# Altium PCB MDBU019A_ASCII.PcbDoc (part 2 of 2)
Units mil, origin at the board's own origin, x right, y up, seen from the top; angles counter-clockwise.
Board outline 2500 x 2300 mil, 2 copper layers (Top Layer, Bottom Layer), stack 62 mil thick; 48 components, 19 nets, 113 pads, 75 vias.
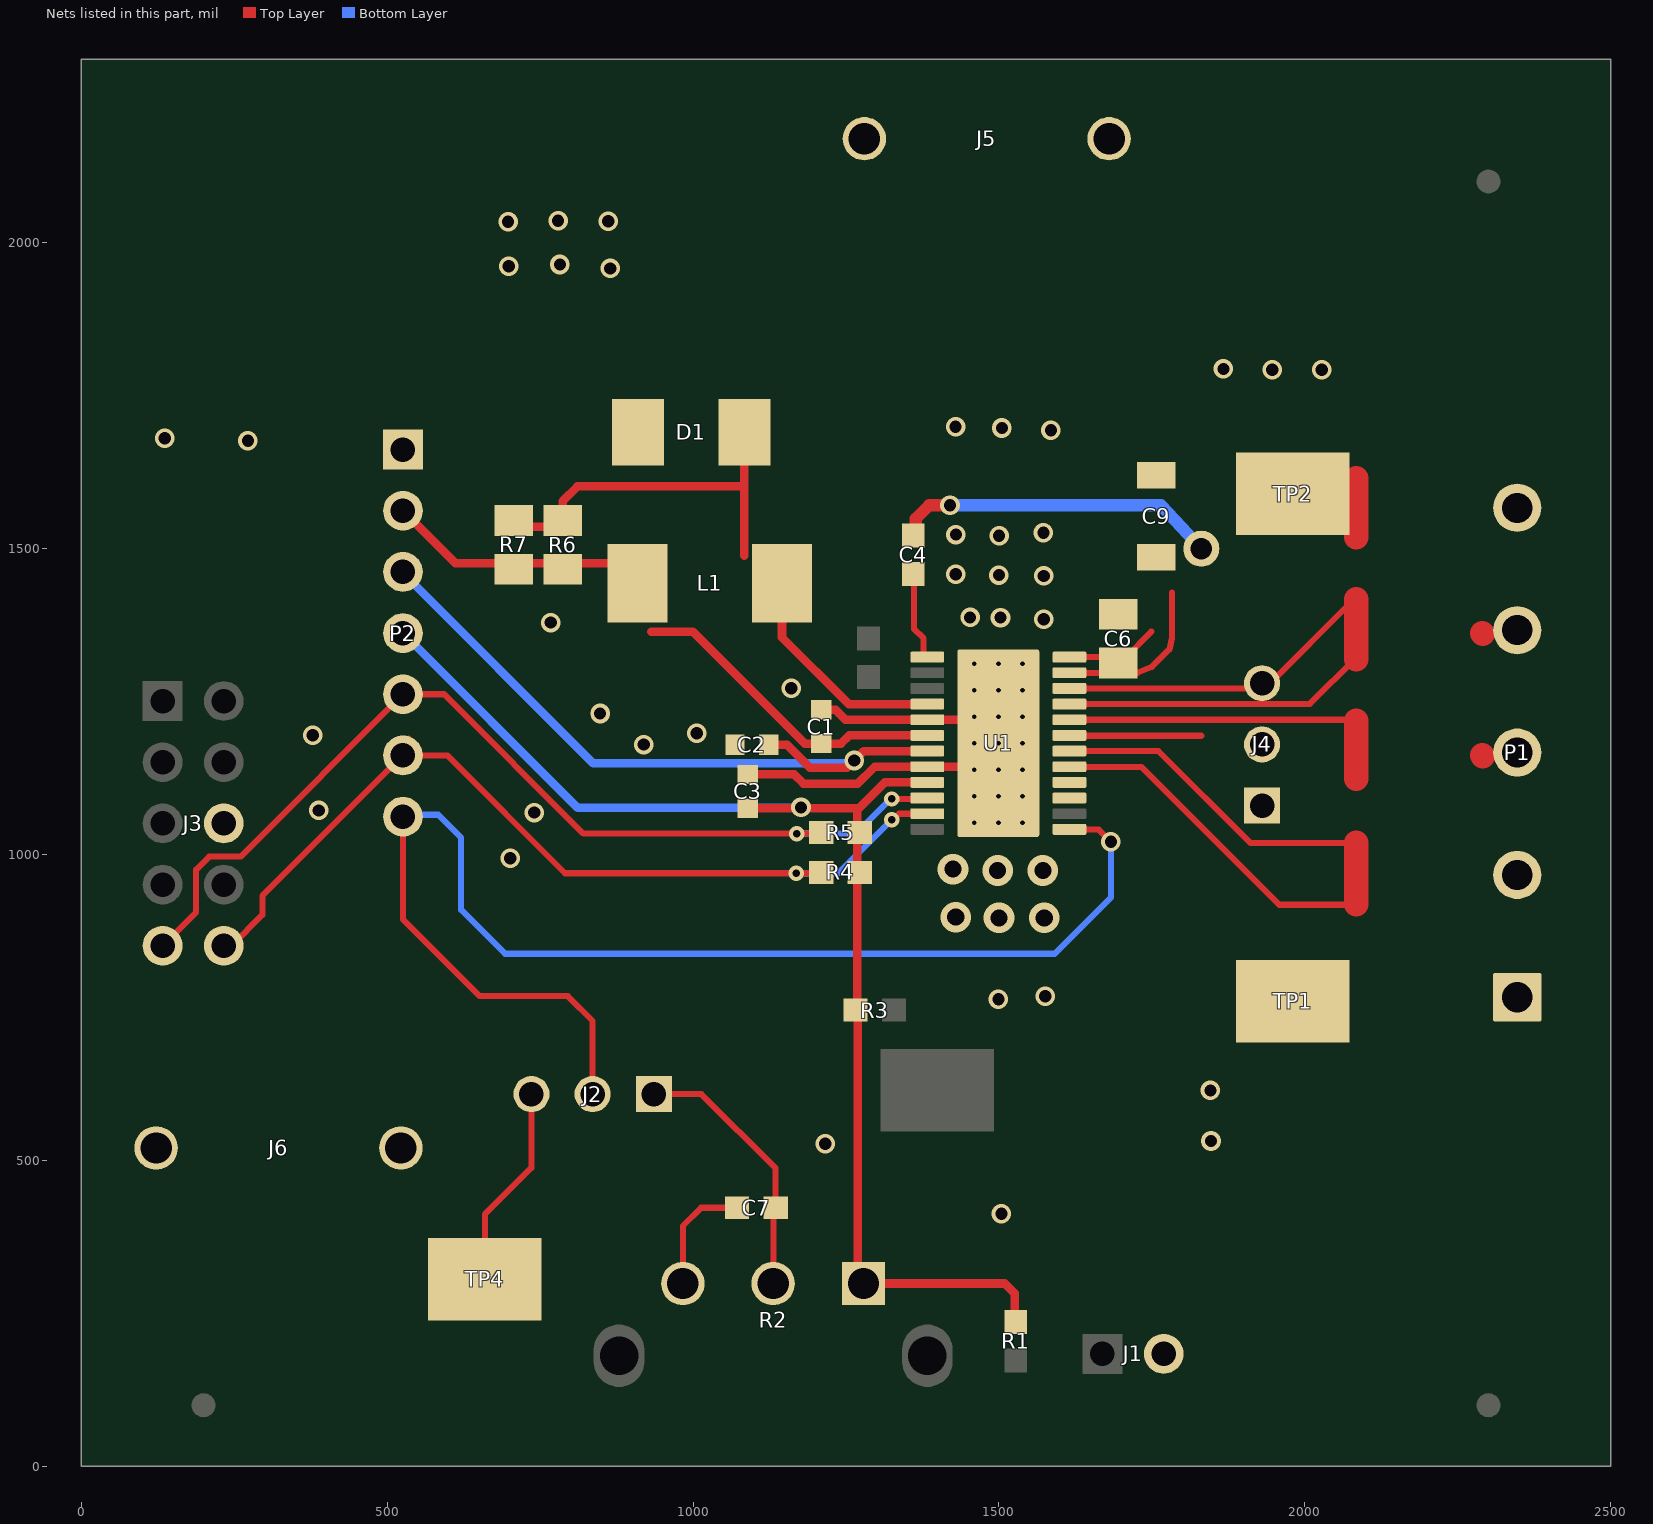
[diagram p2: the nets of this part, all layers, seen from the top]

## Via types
v1: diameter 32, hole 20, Top Layer to Bottom Layer, 44 vias
v2: diameter 19.68, hole 7.87, Top Layer to Bottom Layer, 15 vias
v3: diameter 19.68, hole 7.87, Top Layer to Bottom Layer, tented both sides, 6 vias
v4: diameter 50, hole 28, Top Layer to Bottom Layer, 6 vias
v5: diameter 25, hole 12, Top Layer to Bottom Layer, 4 vias

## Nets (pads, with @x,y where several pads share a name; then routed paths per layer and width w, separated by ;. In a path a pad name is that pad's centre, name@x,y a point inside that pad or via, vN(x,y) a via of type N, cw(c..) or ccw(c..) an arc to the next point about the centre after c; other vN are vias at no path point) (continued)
GND: C1.2 C2.1 C3.1 C6.1 C7.2 C9.2 D1.2 J1.2 J3.6 J5.1 J5.2 J6.1 J6.2 P1.1 P2.1 R2.3 TP1.1 U1.5 U1.8 U1.15 U1.16 U1.25@1499,1182 | length 980.1
  Top Layer w10: R2.3@983.36,299 983.36,392.96 1013.3,422.9 C7.2@1076.08,422.9 ; U1.25@1510,1100 U1.25@1517.7,1092.3 ; U1.25@1510,1110 U1.25@1517.3,1117.3
  Top Layer w14: C3.1@1089.2,1130.99 1165.53,1130.99 1180.49,1116.03 1269.36,1116.03 1295.06,1141.72 ; C1.2@1209.51,1236.59 1232.99,1236.59 1249.19,1220.39 U1.5@1382.86,1220.39 1460.61,1220.39 v2(1499,1182) 1460.61,1143.61 U1.8@1382.86,1143.61 1296.95,1143.61
  Bottom Layer w20: 1481,1095 1486,1090
  other v1: 1504.07,413.03 1216.28,527.43 1846.5,531.89 1845.64,614.54 1499.09,763.65 1575.68,768.64 701.43,994.21 740.3,1068.69 388.16,1072.18 919.43,1179.83 378.28,1195.22 1006.12,1198.24 848.06,1230.54 1160.66,1272.04 767.5,1379.19 1573.05,1384.73 1502.55,1387.35 1452.74,1387.6 1573.3,1455.52 1499.97,1456.81 1429.22,1458.1 1500.23,1520.99 1429.6,1522.97 1572.72,1526.09 272.52,1676.56 136.41,1680.59 1584.85,1693.59 1504.9,1697.24 1429.07,1699.42 1946.61,1792.44 2027.41,1792.44 1866.86,1793.76 864.78,1957.97 698.64,1961.44 782.45,1964.42 697.65,2034.35 861.51,2035.16 779.48,2035.84
  other v2: 1459.63,1095.39 1499,1095.39 1538.37,1095.39 1459.63,1138.69 1499,1138.69 1538.37,1138.69 1459.63,1182 1538.37,1182 1459.63,1225.31 1499,1225.31 1538.37,1225.31 1459.63,1268.61 1499,1268.61 1538.37,1268.61
  other v3: 1459.63,1052.08 1499,1052.08 1538.37,1052.08 1459.63,1311.92 1499,1311.92 1538.37,1311.92
  other v4: 1500.01,896.65 1574.03,896.65 1429.3,897.76 1497.8,973.99 1571.82,973.99 1424.88,976.2
NetC7_1: C7.1 J2.1 R2.2 | length 483.1
  Top Layer w10: J2.1@935.93,608.59 1013.57,608.59 1134.84,487.32 C7.1@1134.84,419.25 ; R2.2@1118.39,286.39 1113.16,286.39 1113.16,306.39 1123.61,316.84 R2.2@1125.52,316.84 ; R2.2@1131,299 1131.2,299.2 C7.1@1131.2,422.9
PWMIN: J2.3 TP4.1 | length 340.5
  Top Layer w10: TP4.1@629.24,311.31 TP4.1@633.47,307.09 ; TP4.1@659.68,305.63 659.68,411.96 735.93,488.2 J2.3@735.93,608.59
SCL: J3.9 P2.5 R5.2 U1.10 | length 1621.2
  Top Layer w10: J3.9@133.08,851 187.76,905.68 187.76,975.54 209.03,996.82 260.7,996.82 P2.5@525.93,1262.05 593.12,1262.05 820.87,1034.3 v5(1169.36,1034.3) 1211.74,1034.3 R5.2@1213.44,1036 ; v5(1325,1091) 1381.43,1091 U1.10@1382.86,1092.43
  Bottom Layer w10: v5(1169.36,1034.3) 1266.46,1034.3 ; 1268.59,1036.43 1323.16,1091 v5(1325,1091)
SDA: J3.10 P2.6 R4.2 U1.11 | length 1463.5
  Top Layer w10: J3.10@233.08,851 245.75,851 296.24,901.48 296.24,932.36 P2.6@525.93,1162.05 598.2,1162.05 790.73,969.52 v5(1168.49,969.52) 1211.96,969.52 R4.2@1213.44,971 ; P2.6@535,1188.82 P2.6@535,1190 ; v5(1325,1057) 1326.84,1057 1336.68,1066.84 U1.11@1382.86,1066.84
  Bottom Layer w10: v5(1168.49,969.52) 1237.52,969.52 v5(1325,1057)
SPEED: J2.2 P2.7 U1.13 | length 2285.8
  Top Layer w10: P2.7@525.93,1062.05 525.93,894.1 651.22,768.81 795.14,768.81 835.93,728.03 J2.2@835.93,608.59 ; U1.13@1615.14,1041.25 1658.11,1041.25 1658.59,1040.77 1663.23,1040.77 v1(1683,1021)
  Bottom Layer w10: P2.7@525.93,1062.05 P2.7@525.93,1038.5 ; P2.7@530.03,1034.4 P2.7@525.93,1038.5 ; v1(1683,1021) 1683,929.63 1591.22,837.86 692.77,837.86 620.95,909.69 620.95,1027.71 583.51,1065.15 499.28,1065.15 P2.7@525.93,1038.5
SW: D1.1 L1.2 R6.2 R7.2 U1.4 | length 955.9
  Top Layer w14: R7.2@707.14,1535.56 R6.2@756.58,1535.56 ; R6.2@787.14,1535.56 787.14,1577.72 811.18,1601.76 1083.8,1601.76 ; 1083.8,1488.63 1083.8,1601.76 ; D1.1@1083.8,1690.24 1083.8,1601.76 ; L1.2@1145.55,1428.46 1145.41,1355.05 1254.49,1245.98 U1.4@1382.86,1245.98
U: J4.1 P1.2 U1.17 U1.18 | length 1202.6
  Top Layer w10: U1.17@1611.7,1143.3 1732.7,1143.3 1958,918 2083,918 ; U1.18@1611.7,1169.3 1760.7,1169.3 1911,1019 2084,1019 ; 2083,916 2084,917 2084,919
  Top Layer w40: 2084,919 2084,967 2084,1019
V: J4.2 P1.3 U1.19 U1.20 | length 781.8
  Top Layer w10: U1.19@1611.7,1194.3 1830.7,1194.3 ; U1.20@1611.7,1220.3 2074.3,1220.3 2075,1221 ; 2084,1124 2086,1122
  Top Layer w40: 2084,1124 2084,1162 2084,1219 ; 2290,1162 2291,1161
V1P8: C2.2 P2.3 U1.7 | length 1155.6
  Top Layer w14: C2.2@1124.3,1179.45 1153.61,1179.45 1190.82,1142.24 1251.96,1142.24 v1(1263.52,1153.8) 1278.92,1169.2 U1.7@1382.86,1169.2
  Bottom Layer w14: P2.3@525.93,1462.05 525.93,1460.04 836.98,1148.99 1258.71,1148.99 v1(1263.52,1153.8)
V3P3: C3.2 P2.4 R1.1 R2.1 R3.1 R4.1 R5.1 U1.9 | length 2151.4
  Top Layer w10: R3.1@1268.56,746.88 R3.1@1269.44,746 ; R1.1@1525.73,234.09 R1.1@1527.41,232.42
  Top Layer w14: C3.2@1089.22,1075.85 1271.18,1075.85 1313.68,1118.34 1336.32,1118.34 1336.64,1118.02 U1.9@1382.86,1118.02 ; R3.1@1268.56,746.88 1268.56,971 1268.56,1036 1268.56,1073.22 ; R2.1@1269.44,308.2 R3.1@1269.44,746 ; R2.1@1278.64,299 1509.45,299 1525.73,282.72 R1.1@1525.73,234.09
  Bottom Layer w14: P2.4@525.93,1362.05 811.37,1076.6 1176.89,1076.6 v1(1176.45,1077.04)
VCC: C4.1 C6.2 C9.1 P1.5 pad.0 TP2.1 U1.23 U1.24 | length 1066.5
  Top Layer w10: U1.24@1603,1322.91 1707.91,1322.91 1748.92,1364.55 ; U1.23@1610.7,1296.9 1610.8,1297 1726,1297 1750.07,1306.78 1778.57,1335.28 1783,1354 1783,1428 ; 2089,1559 2090,1560
  Top Layer w20: C4.1@1364,1525 1364,1549 1386,1571 v1(1420,1571)
  Top Layer w40: 2084,1519 2084,1615
  Bottom Layer w20: v1(1420,1571) 1765,1571 pad.0@1830.74,1500
VCP: C4.2 U1.1 | length 143.6
  Top Layer w10: C4.2@1361,1460 1361,1369 1376.72,1353.28 U1.1@1376.72,1322.91
VREG: C1.1 L1.1 P2.2 R6.1 R7.1 U1.6 | length 964.6
  Top Layer w14: P2.2@525.93,1562.05 611.47,1476.51 707.14,1476.51 787.14,1476.51 876.29,1476.51 L1.1@909.19,1443.61 ; 931.7,1364.08 999.87,1364.08 1182.48,1181.47 C1.1@1209.51,1181.47 1241.85,1181.47 1255.17,1194.8 U1.6@1382.86,1194.8
W: J4.3 P1.4 U1.21 U1.22 | length 1139.8
  Top Layer w10: U1.22@1610.7,1271.3 1934.3,1271.3 2084,1421 ; U1.21@1611.7,1246.3 2008.3,1246.3 2084,1322 ; 2083,1418 2084,1417
  Top Layer w40: 2084,1319 2084,1322 2084,1362 2084,1417 ; 2290,1362 2291,1361
pads on no net: FID1.1 FID2.1 FID3.1 H9.0 H10.0 H11.0 H12.0 J3.1 J3.2 J3.3 J3.4 J3.5 J3.7 J3.8 LBL1.0 R2.MH1 R2.MH2 SH-J1.0 SH-J2.0 U1.25@1499,1182
copper on no net: | length 60632.3
  Top Layer w1: 13128.26,7017.05 13227.94,7116.73 13347.94,7236.73 13467.94,7356.73 13587.94,7476.73 13707.94,7596.73 13827.94,7716.73 ; 13128.26,7077.05 13167.94,7116.73 13287.94,7236.73 13407.94,7356.73 13527.94,7476.73 13647.94,7596.73 13767.94,7716.73 ; 13128.26,7137.05 13227.94,7236.73 13347.94,7356.73 13467.94,7476.73 13587.94,7596.73 13707.94,7716.73 ; 13128.26,7197.05 13167.94,7236.73 13287.94,7356.73 13407.94,7476.73 13527.94,7596.73 13647.94,7716.73 ; 13128.26,7257.05 13227.94,7356.73 13347.94,7476.73 13467.94,7596.73 13587.94,7716.73 ; 13128.26,7317.05 13167.94,7356.73 13287.94,7476.73 13407.94,7596.73 13527.94,7716.73 ; 13128.26,7377.05 13227.94,7476.73 13347.94,7596.73 13467.94,7716.73 ; 13128.26,7437.05 13167.94,7476.73 13287.94,7596.73 13407.94,7716.73 ; 13128.26,7497.05 13227.94,7596.73 13347.94,7716.73 ; 13128.26,7557.05 13167.94,7596.73 13287.94,7716.73 ; 13128.26,7617.05 13227.94,7716.73 ; 13128.26,7677.05 13167.94,7716.73 ; 13167.94,6996.73 13287.94,7116.73 13407.94,7236.73 13527.94,7356.73 13647.94,7476.73 13767.94,7596.73 13887.94,7716.73 ; 13227.94,6996.73 13347.94,7116.73 13467.94,7236.73 13587.94,7356.73 13707.94,7476.73 13827.94,7596.73 13947.94,7716.73 ; 13287.94,6996.73 13407.94,7116.73 13527.94,7236.73 13647.94,7356.73 13767.94,7476.73 13887.94,7596.73 14007.94,7716.73 ; 13347.94,6996.73 13467.94,7116.73 13587.94,7236.73 13707.94,7356.73 13827.94,7476.73 13947.94,7596.73 14067.94,7716.73 ; 13407.94,6996.73 13527.94,7116.73 13647.94,7236.73 13767.94,7356.73 13887.94,7476.73 14007.94,7596.73 14127.94,7716.73 ; 13467.94,6996.73 13587.94,7116.73 13707.94,7236.73 13827.94,7356.73 13947.94,7476.73 14067.94,7596.73 14187.94,7716.73 ; 13527.94,6996.73 13647.94,7116.73 13767.94,7236.73 13887.94,7356.73 14007.94,7476.73 14127.94,7596.73 14247.94,7716.73 ; 13587.94,6996.73 13707.94,7116.73 13827.94,7236.73 13947.94,7356.73 14067.94,7476.73 14187.94,7596.73 14247.94,7656.73 ; 13647.94,6996.73 13767.94,7116.73 13887.94,7236.73 14007.94,7356.73 14127.94,7476.73 14247.94,7596.73 ; 13707.94,6996.73 13827.94,7116.73 13947.94,7236.73 14067.94,7356.73 14187.94,7476.73 14247.94,7536.73 ; 13767.94,6996.73 13887.94,7116.73 14007.94,7236.73 14127.94,7356.73 14247.94,7476.73 ; 13827.94,6996.73 13947.94,7116.73 14067.94,7236.73 14187.94,7356.73 14247.94,7416.73 ; 13887.94,6996.73 14007.94,7116.73 14127.94,7236.73 14247.94,7356.73 ; 13947.94,6996.73 14067.94,7116.73 14187.94,7236.73 14247.94,7296.73 ; 14007.94,6996.73 14127.94,7116.73 14247.94,7236.73 ; 14067.94,6996.73 14187.94,7116.73 14247.94,7176.73 ; 14127.94,6996.73 14247.94,7116.73 ; 14187.94,6996.73 14247.94,7056.73
  Top Layer w15: 9779.12,7116.73 10189.03,7116.73 11048.8,7116.73 11908.56,7116.73 12558.4,7116.73 13128.26,7116.73 14247.94,7116.73 ; 9779.12,7236.73 10189.03,7236.73 11048.8,7236.73 11908.56,7236.73 12558.4,7236.73 13128.26,7236.73 14247.94,7236.73 ; 9779.12,7356.73 10189.03,7356.73 11048.8,7356.73 11908.56,7356.73 12558.4,7356.73 13128.26,7356.73 14247.94,7356.73 ; 9779.12,7476.73 10189.03,7476.73 11048.8,7476.73 11908.56,7476.73 12558.4,7476.73 13128.26,7476.73 14247.94,7476.73 ; 9779.12,7596.73 10189.03,7596.73 11048.8,7596.73 11908.56,7596.73 12558.4,7596.73 13128.26,7596.73 14247.94,7596.73 ; 9779.12,7716.73 14247.94,7716.73 ; 10189.03,7836.73 10189.03,6996.73 ; 11048.8,7836.73 11048.8,6996.73 ; 11908.56,7836.73 11908.56,6996.73 ; 12558.4,7836.73 12558.4,6996.73 ; 13128.26,7836.73 13128.26,6996.73 ; 10189.03,6996.73 9779.12,6996.73 9779.12,7836.73 14247.94,7836.73 14247.94,6996.73 13128.26,6996.73 ; 10189.03,6996.73 11048.8,6996.73 ; 11048.8,6996.73 11908.56,6996.73 ; 11908.56,6996.73 12558.4,6996.73 ; 12558.4,6996.73 13128.26,6996.73
  other v1: 2232.32,557.66

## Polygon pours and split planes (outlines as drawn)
GND on Bottom Layer "Bottom Layer-GND" (solid, remove dead copper, pour order 6): 0,0 0,2500 2500,2500 2500,0
GND on Top Layer "Top Layer-GND" (solid, remove dead copper, pour order 4): -8.85,-18.07 -8.85,2281.93 2491.15,2281.93 2491.15,-18.07

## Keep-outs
Keep-Out Layer:
  lines w10: -5,-5 2505,-5 2505,2305 -5,2305 -5,-5
  text ".Layer_Name" at 577,-858.49 h60

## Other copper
Top Layer:
  rectangle net GND: 1553,1120 1605.99,1123.28
  rectangle net GND: 1553,1084 1601,1125
  text "Layer" at 9839.12,7746.73 h60
  text "Name" at 10249.03,7746.73 h60
  text "Material" at 11108.8,7746.73 h60
  text "Thickness" at 11968.56,7746.73 h60
  text "Constant" at 12618.4,7746.73 h60
  text "Board Layer Stack" at 13188.26,7746.73 h60
  text "1" at 9839.12,7626.73 h60
  text "Top Overlay" at 10249.03,7626.73 h60
  text "2" at 9839.12,7506.73 h60
  text "Top Solder" at 10249.03,7506.73 h60
  text "Solder Resist" at 11108.8,7506.73 h60
  text "0.40mil" at 11968.56,7506.73 h60
  text "3.5" at 12618.4,7506.73 h60
  text "3" at 9839.12,7386.73 h60
  text "Top Layer" at 10249.03,7386.73 h60
  text "Copper" at 11108.8,7386.73 h60
  text "1.40mil" at 11968.56,7386.73 h60
  text "4" at 9839.12,7266.73 h60
  text "Dielectric1" at 10249.03,7266.73 h60
  text "FR-4" at 11108.8,7266.73 h60
  text "59.20mil" at 11968.56,7266.73 h60
  text "4.8" at 12618.4,7266.73 h60
  text "5" at 9839.12,7146.73 h60
  text "Bottom Layer" at 10249.03,7146.73 h60
  text "Copper" at 11108.8,7146.73 h60
  text "1.40mil" at 11968.56,7146.73 h60
  text "6" at 9839.12,7026.73 h60
  text "Bottom Solder" at 10249.03,7026.73 h60
  text "Solder Resist" at 11108.8,7026.73 h60
  text "0.40mil" at 11968.56,7026.73 h60
  text "3.5" at 12618.4,7026.73 h60
  text ".Layer_Name" at 577,-858.49 h60
Bottom Layer:
  rectangle net GND: 1454,1067 1549,1297
  text ".VersionControl_RevNumber" at 4074,1205 h60
  text "UL94V-0" at 3115,1048 h60
  text "SVN:" at 4170,179.5 h60
  text ".Layer_Name" at 577,-858.49 h60

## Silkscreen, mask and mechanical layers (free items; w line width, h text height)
Top Overlay:
  rectangle: 1323.17,1364.28 1363.17,1404.28
  rectangle: 2180,240 2330,390
  rectangle: 2180,430 2330,580
  lines w10: 1399.17,938.18 656.69,937.26 656.96,1402.64 656.81,1827.69 1777.62,1827.99 1777.98,1659.11 ; 1600.22,936.02 1776.3,936.25 ; 1776.17,936.46 1777.98,1445.26
  text "GND" at 1400,2090 h40
  text "MDBU019A" at 67.16,1985.98 h30
  text "VCC" at 1919.91,1704.5 h40
  text "GND" at 356.89,1645.05 h35
  text "VREG" at 304.51,1549.26 h40
  text "V1P8" at 355.6,1470.19 h25
  text "V3P3" at 362.4,1345.27 h27
  text "W" at 2003,1265 h40
  text "SC" at 398.24,1243.27 h35
  text "V" at 2000,1157 h40
  text "SD" at 404.5,1136.37 h35
  text "U" at 2005,1062 h40
  text "SPEED" at 365.02,1043.05 h20
  text "GND" at 1940,620 h40
  text "PWMIN" at 617.44,521.2 h20
  text "SPEED" at 789.32,518.29 h20
  text "ANALOG" at 946.73,516.47 h20
  text "Sleep" at 1930,490 h45
  text "FG" at 1365.39,479.83 h40
  text "Stand-By" at 1810,300 h45
  text "PWMIN" at 565.01,154.15 h40
  text "DIR-GND" at 1591.87,67.56 h40
  text ".Layer_Name" at 577,-858.49 h60
Bottom Overlay:
  text ".Layer_Name" at 577,-858.49 h60
Top Paste:
  text ".Layer_Name" at 577,-858.49 h60
Bottom Paste:
  text ".Layer_Name" at 577,-858.49 h60
Top Solder:
  text ".Layer_Name" at 577,-858.49 h60
  text ".Layer_Name" at 577,-858.49 h60
Bottom Solder:
  text ".Layer_Name" at 577,-858.49 h60
Drill Guide:
  text ".Layer_Name" at 577,-858.49 h60
M1 Board Outline:
  the board outline again, w10
  text ".Layer_Name" at 577,-858.49 h60
M2 Board Dimensions:
  rectangle: 124.5,-410.5 499.5,-285.5
  rectangle: -0.5,-285.5 124.5,-160.5
  lines w7: -0.5,-285.5 999.5,-285.5 ; 124.5,-410.5 124.5,-160.5 ; 249.5,-410.5 249.5,-160.5 ; 499.5,-410.5 499.5,-160.5 ; 749.5,-410.5 749.5,-160.5 ; -0.5,-410.5 -0.5,-160.5 999.5,-160.5 999.5,-410.5 -0.5,-410.5
  text ".Layer_Name" at 577,-858.49 h60
M3 3D STEP Top:
  text ".Layer_Name" at 577,-858.49 h60
M4 3D STEP Bottom:
  text ".Layer_Name" at 577,-858.49 h60
M5 Assembly Top:
  lines w10: -292,-930.17 6308,-930.17 ; -292,-726.83 6310,-726.83 ; -292,-523.5 -292,-1133.5 3713,-1133.5 6310,-1133.5 6310,-523.5 -291.5,-523.5 -291.5,-1133.5 1284,-1133.5 ; 2173,-1133.5 2173,-523.5 ; 3440,-726.83 3440,-523.5 ; 4280,-726.83 4280,-523.5 ; 4902,-1140 4902,-937.17
  text "COMPONENTS MARKED 'DNP' SHOULD NOT BE POPULATED." at 1153.5,-318.5 h60
  text "ASSEMBLY VARIANT:" at 1153,-434 h60
  text ".VariantName" at 2189,-434 h60
  text "PCB VIEWED FROM TOP SIDE" at -228.5,-655.67 h60
  text "BOARD #:" at 2248,-655.67 h60
  text ".PRJ_Number" at 2793.5,-655.67 h60
  text "REV:" at 3638,-655.67 h60
  text ".PCB_Rev" at 3929.5,-655.67 h60
  text "SVN REV:" at 4476,-655.67 h60
  text ".VersionControl_RevNumber" at 4982,-655.67 h60
  text "IGNORE ->" at -228.5,-858.49 h60
  text "PLOT NAME =" at -228.5,-1064.34 h60
  text ".plot_File_Name" at 577,-1064.34 h60
  text "GENERATED    :" at 2250,-1064.34 h60
  text ".Print_Date" at 3119.5,-1064.34 h60
  text ".Print_Time" at 3848.5,-1064.34 h60
  text "TEXAS INSTRUMENTS" at 5113,-1064.34 h60
M6 Assembly Bottom:
  lines w10: -292.5,-727.33 6309.5,-727.33 ; -290.5,-930.67 6309.5,-930.67 ; 1115.5,-1140.5 1115.5,-937.67 ; 1737.5,-727.33 1737.5,-524 ; 2577.5,-727.33 2577.5,-524 ; 3844.5,-1134 3844.5,-524 ; 4733.5,-1134 6309,-1134 6309,-524 -292.5,-524 -292.5,-1134 2304.5,-1134 6309.5,-1134 6309.5,-524
  text "COMPONENTS MARKED 'DNP' SHOULD NOT BE POPULATED." at 6102,-318 h60
  text ".VariantName" at 5058,-434 h60
  text "ASSEMBLY VARIANT:" at 6097,-434 h60
  text ".VersionControl_RevNumber" at 1035.5,-656.17 h60
  text "SVN REV:" at 1541.5,-656.17 h60
  text ".PCB_Rev" at 2088,-656.17 h60
  text "REV:" at 2379.5,-656.17 h60
  text ".PRJ_Number" at 3224,-656.17 h60
  text "BOARD #:" at 3769.5,-656.17 h60
  text "PCB VIEWED FROM BOTTOM SIDE" at 6246,-656.17 h60
  text "IGNORE ->" at 2547.85,-858.49 h60
  text "TEXAS INSTRUMENTS" at 904.5,-1064.84 h60
  text ".Print_Time" at 2169,-1064.84 h60
  text ".Print_Date" at 2898,-1064.84 h60
  text "GENERATED    :" at 3767.5,-1064.84 h60
  text ".plot_File_Name" at 5440.5,-1064.84 h60
  text "PLOT NAME =" at 6246,-1064.84 h60
M9 Title Sheet:
  lines w10: -491.5,1041.5 -291.5,1041.5 ; -491.5,3416.5 -291.5,3416.5 ; -491.5,5791.5 -291.5,5791.5 ; 2008.5,-1333.5 2008.5,-1133.5 ; 2008.5,7966.5 2008.5,8166.5 ; 4508.5,-1333.5 4508.5,-1133.5 ; 4508.5,7966.5 4508.5,8166.5 ; 6321,-1133.5 6321,-523.5 11303.5,-523.5 ; 7008.5,-1333.5 7008.5,-1133.5 ; 7008.5,7966.5 7008.5,8166.5 ; 9508.5,-1333.5 9508.5,-1133.5 ; 11303.5,-1133.5 11303.5,-523.5 ; 11303.5,-823.5 14303.5,-823.5 ; 11303.5,-223.5 14303.5,-223.5 ; 11304.5,370.5 14304.5,370.5 ; 12008.5,-1333.5 12008.5,-1133.5 ; 12808.5,-1123.5 12808.5,-523.5 ; 14303.5,-523.5 11303.5,-523.5 ; 14303.5,76.5 11303.5,76.5 ; 14308.5,66.5 14308.5,-1133.5 ; 14308.5,871 11304.5,871 11303.5,871 11303.5,370.5 11303.5,76.5 ; 14308.5,1041.5 14508.5,1041.5 ; 14308.5,3416.5 14508.5,3416.5 ; 14308.5,5791.5 14508.5,5791.5 ; 11303.5,-523.5 11303.5,76.5 ; 14308.5,-1133.5 -291.5,-1133.5 -291.5,7966.5 14308.5,7966.5 14308.5,-1133.5 ; -491.5,-1333.5 14508.5,-1333.5 14508.5,8166.5 -491.5,8166.5 -491.5,-1333.5
  text "1" at 739.84,8036.5 h70
  text "2" at 3235.5,8036.5 h70
  text "3" at 5724.84,8036.5 h70
  text "4" at 8231.51,8036.5 h70
  text "A" at -416.5,6893.5 h70
  text "A" at 14383.5,6893.5 h70
  text "B" at -416.5,4513.5 h70
  text "B" at 14383.5,4513.5 h70
  text "C" at -416.5,2138.5 h70
  text "C" at 14383.5,2138.5 h70
  text "PROJECT TITLE:" at 11343.5,277.5 h45
  text ".PRJ_Title" at 11393.5,144.17 h70
  text "DESIGNED FOR:" at 11343.5,-23.5 h45
  text ".PRJ_Customer" at 11393.5,-163.5 h70
  text "D" at -416.5,-231.5 h70
  text "D" at 14383.5,-231.5 h70
  text "FILE NAME:" at 11343.5,-323.5 h45
  text ".PCB_File_Name_No_Path" at 11393.5,-443.5 h70
  text "Texas Instruments (TI) and/or its licensors do not warrant the accuracy or completeness of this specification" at 6374,-605.34 h45
  text "ENGINEER:" at 11343.5,-613.5 h45
  text "LAYOUT BY:" at 12848.5,-613.5 h45
  text "or any information contained therein. TI and/or its licensors do not warrant that this design will meet" at 6329.01,-718 h45
  text ".PRJ_Engineer" at 11393.5,-768.49 h70
  text ".PCB_Layout" at 12899,-768.49 h70
  text "the specifications, will be suitable for your application or fit for any particular purpose, or will operate in" at 6329.01,-830.67 h45
  text ".Layer_Name" at 577,-858.49 h60
  text "ALTIUM DESIGNER VERSION:" at 12848.5,-923.5 h45
  text "an implementation. TI and/or its licensors do not warrant that the design is production worthy. You should" at 6329.01,-943.33 h45
  text "completely validate and test your design implementation to confirm the system functionality for your application." at 6374,-1056 h45
  text ".print_Scale" at 11393.5,-1056.83 h70
  text ".Application_BuildNumber" at 12899,-1056.83 h70
  text "1" at 739.84,-1263.5 h70
  text "2" at 3235.5,-1263.5 h70
  text "3" at 5724.84,-1263.5 h70
  text "4" at 8231.51,-1263.5 h70
  text "5" at 10730.5,-1263.5 h70
  text "6" at 13235.5,-1263.5 h70
M10 Fab Notes:
  drawing of 212 lines, arcs and shapes, not listed
  text "DESIGN INFORMATION" at 12381.02,6810 h60
  text "(REFER ALSO ARRAY/PANEL PROFILING INFORMATION)" at 12019.46,6648.29 h60
  text "BOARD SIZE" at 11333.46,6644 h60
  text "2500MIL" at 11795.78,6516.18 h60
  text "X" at 12301.46,6516.18 h60
  text "2300MIL" at 12532.78,6516.18 h60
  text "Number of Layers :" at 11736.46,6319 h60
  text "2" at 12831.27,6309 h60
  text "MIN. TRACK WIDTH:" at 11736.46,6180 h60
  text "10" at 12832.7,6180 h60
  text "MIL" at 12987.46,6180 h60
  text "MIN. CLEARANCE:" at 11736.46,6048 h60
  text "8" at 12832.7,6048 h60
  text "MIL" at 12987.46,6048 h60
  text "MIN. VIA PAD SIZE:" at 11736.46,5916 h60
  text "24" at 12802.71,5916 h60
  text "MIL" at 12987.46,5916 h60
  text "0.05mm (2MIL)" at 12431.46,5774.29 h60
  text "MINIMUM ANNULAR RING" at 11407.23,5770 h60
  text "EXTERNAL" at 13139.46,5770 h60
  text "PER" at 11607.23,5652 h60
  text "IPC-D-275 CLASS 2 LEVEL C" at 11827.23,5652 h60
  text "MIL, HOLES" at 13315.46,5539.71 h60
  text "+/-" at 12923,5539 h60
  text "+/-" at 13777,5539 h60
  text "REGISTRATION TOLERANCES:" at 11407.23,5534 h60
  text "METAL" at 12607,5534 h60
  text "5" at 13183.2,5534 h60
  text "3" at 14016.2,5534 h60
  text "MIL" at 14132.46,5534 h60
  text "MATERIAL:" at 11332.46,5324.54 h60
  text "FR-4 High Tg" at 12318.9,5184.21 h60
  text "FR-408" at 11753.46,5175.64 h60
  text "X" at 12165.46,5175.64 h60
  text "OTHER" at 13241.46,5175.64 h60
  text "62 MIL (1.6mm) +/-10%" at 12073.56,5012.92 h60
  text "THICKNESS:" at 11407.23,5008.64 h60
  text "X" at 11945.4,5008.64 h60
  text "OTHER" at 13358.46,5008.64 h60
  text "TOLERANCE:" at 11407.23,4850.64 h60
  text "X" at 12246.53,4850.64 h60
  text "ANSI IPC-6012 TYPE 3 CLASS 2" at 12433.48,4850.64 h60
  text "OTHER +/-" at 12433.46,4694.64 h60
  text "BOW & TWIST:" at 11407.23,4537.64 h60
  text "X" at 12246.53,4537.64 h60
  text "ANSI IPC-6012 TYPE 3 CLASS 2" at 12433.48,4537.64 h60
  text "OTHER +/-" at 12433.46,4379.13 h60
  text "COPPER THICKNESS (FINISHED):" at 11332.46,4243.64 h60
  text "1.4MIL (1oz)" at 12212.46,4090.92 h60
  text "2MIL (1.4oz)" at 12979.46,4090.92 h60
  text "2.8MIL (2oz)" at 13706.46,4090.92 h60
  text "OUTER:" at 11689.46,4086.64 h60
  text "X" at 12084,4086 h60
  text "1.4MIL (1oz)" at 12212.46,3933.92 h60
  text "2.8MIL (2oz)" at 12979.46,3933.92 h60
  text "N/A" at 13706,3934.29 h60
  text "INNER SIGNAL:" at 11400.38,3929.64 h60
  text "X" at 12085.42,3929.64 h60
  text "DRILLING:" at 11332.46,3790.64 h60
  text "REFERENCE:" at 11407.23,3673.64 h60
  text "X" at 12055.46,3673.64 h60
  text "AS SHOWN" at 12242.46,3673.64 h60
  text "X" at 12956.46,3673.64 h60
  text "NC_DRILL FILES" at 13093.46,3673.64 h60
  text "PTH MIN COPPER THICKNESS:" at 11407.23,3515.64 h60
  text "X" at 12757.46,3515.64 h60
  text "1MIL" at 12894.46,3515.64 h60
  text "OTHER" at 13391.46,3515.64 h60
  text "BOARD FINISH:" at 11332.46,3356.64 h60
  text "SILKSCREEN:" at 11487.68,3238.64 h60
  text "X" at 12436.46,3238.64 h60
  text "TOP" at 12562.46,3238.64 h60
  text "BOTTOM" at 13073.46,3238.64 h60
  text "SILKSCREEN COLOR:" at 11487.68,3071.64 h60
  text "X" at 12435.42,3071.64 h60
  text "WHITE" at 12562.46,3071.64 h60
  text "OTHER" at 13073.46,3071.64 h60
  text "SOLDER RESIST COLOR:" at 11487.68,2901.64 h60
  text "X" at 12055.42,2742.44 h60
  text "GREEN" at 12182.46,2742.44 h60
  text "BLUE" at 12773.46,2742.44 h60
  text "OTHER" at 13311.46,2742.44 h60
  text "IMMERSION GOLD (ENIG)" at 12393.46,2553.92 h60
  text "ENEPIG" at 13731,2550.64 h60
  text "SURFACE FINISH:" at 11332.46,2549.64 h60
  text "X" at 12206.51,2549.64 h60
  text "IMM. TIN/SILVER OR EQUIV" at 11662,2392.64 h60
  text "OTHER" at 13093.46,2392.64 h60
  text "ARRAY/PANEL:" at 11332.46,2213.64 h60
  text "CUT AND TRIM PER MECH LAYER 1" at 12393.46,2209.35 h60
  text "N.C. ROUTE" at 12393.46,2057.64 h60
  text "X" at 13072.46,2057.64 h60
  text "V. SCORE" at 13259.46,2057.64 h60
  text "CERTIFICATION:" at 11332.46,1920.64 h60
  text "MATERIALS AND WORKMANSHIP FOR ALL PCBS" at 12057.46,1920.64 h60
  text "TO MEET OR EXCEED THE REQUIREMENTS OF:" at 12057.46,1822.64 h60
  text "X" at 11683.96,1686.13 h60
  text "ANSI IPC-A-600F CLASS ->" at 11822.96,1686.13 h60
  text "X" at 13462.02,1686.13 h60
  text "2" at 13580.96,1686.14 h60
  text "1" at 13265.96,1684.64 h60
  text "3" at 13934.96,1684.64 h60
  text "X" at 11686.02,1526.64 h60
  text "UL 94V-0" at 11822.96,1526.64 h60
  text "X" at 12498.02,1526.64 h60
  text "RoHS" at 12634.96,1526.64 h60
  text "OTHER" at 13279.36,1526.64 h60
  text "PER ORDER" at 13676.42,1526.64 h60
  text "ADDITIONAL REQUIREMENTS:" at 11332.46,1385.64 h60
  text "MICROSECTION:" at 11407.23,1270.64 h60
  text "YES" at 12312.96,1270.64 h60
  text "REQUIRED" at 13174.46,1114.49 h60
  text "BARE BOARD ELEC. TEST:" at 11407.23,1111.64 h60
  text "NONE" at 12712.96,1111.64 h60
  text "X" at 13047.46,1111.64 h60
  text "PER ORDER" at 13766.46,1111.64 h60
  text "MANUFACTURER'S UL:" at 11407.23,954.64 h60
  text "RAIL" at 12572.96,950.35 h60
  text "METAL" at 13064.77,950.35 h60
  text "X" at 13440,950 h60
  text "SILK" at 13576.46,950.35 h60
  text ".Layer_Name" at 577,-858.49 h60
M11 Gerber Information:
  lines w10: -292,-930.17 6308,-930.17 ; -292,-726.83 6310,-726.83 ; -292,-523.5 -292,-1133.5 3713,-1133.5 6310,-1133.5 6310,-523.5 -291.5,-523.5 -291.5,-1133.5 1284,-1133.5 ; 2173,-1133.5 2173,-523.5 ; 3440,-726.83 3440,-523.5 ; 4280,-726.83 4280,-523.5 ; 4902,-1140 4902,-937.17
  text "ALL ARTWORK VIEWED FROM TOP SIDE" at -228.5,-655.67 h60
  text "BOARD #:" at 2248,-655.67 h60
  text ".PRJ_Number" at 2793.5,-655.67 h60
  text "REV:" at 3638,-655.67 h60
  text ".PCB_Rev" at 3929.5,-655.67 h60
  text "SVN REV:" at 4476,-655.67 h60
  text ".VersionControl_RevNumber" at 4982,-655.67 h60
  text "LAYER NAME =" at -228.5,-858.49 h60
  text "PLOT NAME =" at -228.5,-1064.34 h60
  text ".plot_File_Name" at 577,-1064.34 h60
  text "GENERATED    :" at 2250,-1064.34 h60
  text ".Print_Date" at 3119.5,-1064.34 h60
  text ".Print_Time" at 3848.5,-1064.34 h60
  text "TEXAS INSTRUMENTS" at 5113,-1064.34 h60
M12 Stackup:
  text ".Layer_Name" at 577,-858.49 h60
M13 Component Bodies Top:
  text ".Layer_Name" at 577,-858.49 h60
M14 Component Bodies Bottom:
  text ".Layer_Name" at 577,-858.49 h60
M15 Courtyards Top:
  text ".Layer_Name" at 577,-858.49 h60
M16 Courtyards Bottom:
  text ".Layer_Name" at 577,-858.49 h60
Drill Drawing:
  lines w10: 2599.09,1091.42 2626.72,1105.23 2654.34,1091.42 2640.53,1119.04 2654.34,1146.67 2626.72,1132.86 2599.09,1146.67 2612.9,1119.04 2599.09,1091.42 ; 2599.09,1229.55 2612.9,1229.55 2626.72,1215.74 2640.53,1229.55 2654.34,1229.55 2640.53,1243.36 2654.34,1257.18 2640.53,1257.18 2626.72,1270.99 2612.9,1257.18 2599.09,1257.18 2612.9,1243.36 2599.09,1229.55 ; 2599.09,1395.31 2654.34,1395.31 2626.72,1340.06 2599.09,1395.31 ; 2599.09,1492 2626.72,1464.38 2654.34,1492 2626.72,1519.63 2599.09,1492 ; 2599.09,1602.51 2612.9,1602.51 2612.9,1588.7 2640.53,1588.7 2640.53,1602.51 2654.34,1602.51 2654.34,1630.14 2640.53,1630.14 2640.53,1643.95 2612.9,1643.95 2612.9,1630.14 2599.09,1630.14 2599.09,1602.51 ; 2599.09,1837.34 2599.09,1851.15 2612.9,1864.96 2599.09,1878.78 2599.09,1892.59 2612.9,1892.59 2626.72,1878.78 2640.53,1892.59 2654.34,1892.59 2654.34,1878.78 2640.53,1864.96 2654.34,1851.15 2654.34,1837.34 2640.53,1837.34 2626.72,1851.15 2612.9,1837.34 2599.09,1837.34 ; 2610.14,1102.47 2626.72,1110.76 2643.29,1102.47 2635.01,1119.04 2643.29,1135.62 2626.72,1127.33 2610.14,1135.62 2618.43,1119.04 2610.14,1102.47 ; 2610.14,1235.08 2618.43,1235.08 2626.72,1226.79 2635.01,1235.08 2643.29,1235.08 2635.01,1243.36 2643.29,1251.65 2635.01,1251.65 2626.72,1259.94 2618.43,1251.65 2610.14,1251.65 2618.43,1243.36 2610.14,1235.08 ; 2610.14,1384.26 2643.29,1384.26 2626.72,1351.11 2610.14,1384.26 ; 2610.14,1608.04 2618.43,1608.04 2618.43,1599.75 2635.01,1599.75 2635.01,1608.04 2643.29,1608.04 2643.29,1624.61 2635.01,1624.61 2635.01,1632.9 2618.43,1632.9 2618.43,1624.61 2610.14,1624.61 2610.14,1608.04 ; 2610.14,1848.39 2610.14,1856.68 2618.43,1864.96 2610.14,1873.25 2610.14,1881.54 2618.43,1881.54 2626.72,1873.25 2635.01,1881.54 2643.29,1881.54 2643.29,1873.25 2635.01,1864.96 2643.29,1856.68 2643.29,1848.39 2635.01,1848.39 2626.72,1856.68 2618.43,1848.39 2610.14,1848.39
  lines w12: 2549,1054.12 4527.02,1054.12 ; 2549,2173 4527.02,2173 ; 2886.86,929.8 2886.86,2297.32 ; 3218.86,929.8 3218.86,2297.32 ; 3855.43,929.8 3855.43,2297.32 ; 4114.57,929.8 4114.57,2297.32 ; 2549,929.8 4527.02,929.8 4527.02,2297.32 2549,2297.32 2549,929.8
  text "Symbol" at 2623.59,2210.3 h72
  text "Quantity" at 2924.16,2210.3 h72
  text "Finished Hole Size" at 3256.16,2210.3 h72
  text "Plated" at 3892.72,2210.3 h72
  text "Hole Type" at 4151.86,2210.3 h72
  text "21" at 2924.16,2085.98 h60
  text "7.87mil (0.200mm)" at 3256.16,2085.98 h60
  text "PTH" at 3892.72,2085.98 h60
  text "Round" at 4151.86,2085.98 h60
  text "C" at 2598.31,2075.99 h55.25
  text "4" at 2924.16,1961.66 h60
  text "12.00mil (0.305mm)" at 3256.16,1961.66 h60
  text "PTH" at 3892.72,1961.66 h60
  text "Round" at 4151.86,1961.66 h60
  text "A" at 2598.31,1951.67 h55.25
  text "44" at 2924.16,1837.34 h60
  text "20.00mil (0.508mm)" at 3256.16,1837.34 h60
  text "PTH" at 3892.72,1837.34 h60
  text "Round" at 4151.86,1837.34 h60
  text "6" at 2924.16,1713.02 h60
  text "28.00mil (0.711mm)" at 3256.16,1713.02 h60
  text "PTH" at 3892.72,1713.02 h60
  text "Round" at 4151.86,1713.02 h60
  text "B" at 2598.31,1703.03 h55.25
  text "1" at 2924.16,1588.7 h60
  text "35.43mil (0.900mm)" at 3256.16,1588.7 h60
  text "PTH" at 3892.72,1588.7 h60
  text "Round" at 4151.86,1588.7 h60
  text "25" at 2924.16,1464.38 h60
  text "40.00mil (1.016mm)" at 3256.16,1464.38 h60
  text "PTH" at 3892.72,1464.38 h60
  text "Round" at 4151.86,1464.38 h60
  text "5" at 2924.16,1340.06 h60
  text "49.21mil (1.250mm)" at 3256.16,1340.06 h60
  text "PTH" at 3892.72,1340.06 h60
  text "Round" at 4151.86,1340.06 h60
  text "7" at 2924.16,1215.74 h60
  text "51.18mil (1.300mm)" at 3256.16,1215.74 h60
  text "PTH" at 3892.72,1215.74 h60
  text "Round" at 4151.86,1215.74 h60
  text "2" at 2924.16,1091.42 h60
  text "62.99mil (1.600mm)" at 3256.16,1091.42 h60
  text "PTH" at 3892.72,1091.42 h60
  text "Slot" at 4151.86,1091.42 h60
  text "115 Total" at 2924.16,967.1 h60
  text "Slot definitions :" at 2623.59,880.07 h60
  text "Routed Path Length" at 3074.31,880.07 h60
  text "= Calculated from tool start centre position to tool end centre position." at 3614.05,880.07 h60
  text "Hole Length" at 3074.31,830.35 h60
  text "= Routed Path Length + Tool Size = Slot length as defined in the PCB layout" at 3414.24,830.35 h60
  text ".Layer_Name" at 577,-858.49 h60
